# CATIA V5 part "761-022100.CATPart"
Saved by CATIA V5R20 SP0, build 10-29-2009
Part number: 761-022100
Source: Unknown
Property "ARTICLENO": "761-022100"
Property "BOMINFO": "761-022100"
Property "CODE": "761-022100"
Property "H": "22.000"
Property "L1": "100.000"
Property "L2": "80.000"
Property "LINA": "761-022100"
Property "NB": "761-022100"
Property "NBSYN": "$CODE."
Property "NN": "761"
Property "NT": "VW/AUDI Keys"
Property "P": "4.000"
Property "SUPPLIER": "CF"
Bounding box of the stored display mesh (mm): x -50 to 50, y 0 to 22, z -11 to 11
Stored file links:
  C:\Users\Utente\Desktop\3D files 761\761-022100.CATPart
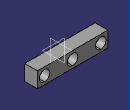
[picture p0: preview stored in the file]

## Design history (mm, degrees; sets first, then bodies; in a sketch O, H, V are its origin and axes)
Body1 "Geometry.1" (main body)
  Solid1 "761-022100.catpart": solid without history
